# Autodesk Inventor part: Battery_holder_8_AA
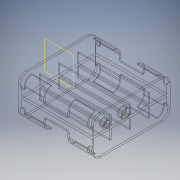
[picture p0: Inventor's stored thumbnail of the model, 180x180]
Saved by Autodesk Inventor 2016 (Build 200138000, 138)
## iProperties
Created: 2016-12
Part Number: Battery_holder_8_AA
Material: Generic
Document SubType Name: Modeling
Designer: jose
Density: 1 g/cm^3
Appearance: Default
Author: jose
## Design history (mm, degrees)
sketch "Sketch4"
  geometry: L1 (0, 0)-(14.542, 0); L2 (14.542, 0)-(14.542, -59.182); L3 (14.542, -59.182)-(0, -59.182); L4 (0, -59.182)-(0, 0)
  constraints: 8 end point, 2 parallel, 1 horizontal, 1 perpendicular
  dimensions: "d5" = 14.5415 distance of L1.start L1.end; "d6" = 59.182 distance of L3.end L1.start
extrude "Extrusion2" new body sketch "Sketch4" distance "d7" = 57.785; taper "d8" = 0 deg
fillet "Fillet1" dims "d9" = 5.842
shell "Shell1" dims "d10" = 1.5748, "d23" = 0.9652
sketch "Sketch5"
  geometry: L1 (19.621, 14.541)-(38.163, 14.541); L2 (38.163, 14.541)-(38.164, 4.318); L3 (38.164, 4.318)-(19.621, 4.318); L4 (19.621, 4.318)-(19.621, 14.541); L5 (28.893, 0)-(28.893, 14.541); L6 (57.785, 0)-(0, 0) reference; L7 (56.21, 14.541)-(1.575, 14.541) reference; L8 (4.369, 14.541)-(1.575, 14.541); L9 (1.575, 14.541)-(1.575, 6.096); L10 (1.575, 6.096)-(4.369, 6.096); L11 (4.369, 6.096)-(4.369, 14.541); L12 (56.21, 14.541)-(53.416, 14.541); L13 (53.416, 14.541)-(53.416, 6.096); L14 (53.416, 6.096)-(56.21, 6.096); L15 (56.21, 6.096)-(56.21, 14.541); L16 (57.785, 8.699)-(57.785, 0) reference; L17 (1.575, 8.699)-(1.575, 0.965) reference; L18 (56.21, 0.965)-(56.21, 8.699) reference
  constraints: 26 end point, 6 collinear, 5 parallel, 3 horizontal, 3 perpendicular, 2 midpoint, 1 point on line, 1 other
  dimensions: "d11" = 4.318 distance between parallel lines of L6 L3; "d12" = 18.542 distance of L1.start L1.end; "d15" = 6.096 distance between parallel lines of L6 L10; "d16" = 2.794 distance of L9.end L10.end
extrude "Extrusion3" cut sketch "Sketch5" stored distance "d13" = 57.785; taper "d14" = 0 deg
fillet "Fillet2" dims "d17" = 1.397
sketch "Sketch6"
  geometry: L1 (0, 4.877)-(0, 52.375) reference; L2 (0, 28.626)-(54.635, 28.626); L3 (54.635, 0)-(54.635, 57.252) reference; L4 (0, 28.118)-(54.635, 28.118); L5 (54.635, 28.118)-(54.635, 29.134); L6 (54.635, 29.134)-(0, 29.134); L7 (0, 29.134)-(0, 28.118); L8 (0, 13.386)-(54.635, 13.386); L9 (54.635, 13.386)-(54.635, 14.402); L10 (54.635, 14.402)-(0, 14.402); L11 (0, 14.402)-(0, 13.386); L12 (0, 42.85)-(54.635, 42.85); L13 (54.635, 42.85)-(54.635, 43.866); L14 (54.635, 43.866)-(0, 43.866); L15 (0, 43.866)-(0, 42.85); 1 further point
  constraints: 26 end point, 6 parallel, 6 point on line, 3 horizontal, 3 perpendicular, 2 collinear, 2 midpoint, 1 other
  dimensions: "d18" = 1.016 distance between parallel lines of L6 L4; "d19" = 13.716 distance between parallel lines of L10 L4; "d20" = 13.716 distance between parallel lines of L12 L6
extrude "Extrusion4" join sketch "Sketch6" distance "d21" = 7.4168; taper "d22" = 0 deg
sketch "Sketch8"
  geometry: L1 (0, 0.965)-(0, 0) reference; L2 (47.498, 0.965)-(0, 0.965) reference; L3 (-4.877, -4.877)-(-4.877, -9.258) reference; L4 (0, 0.457)-(0, 0); A1 r 5.355 centre (0.479, -4.877) between (0, 0.457) and (-4.877, -4.877); A2 r 4.877 centre (0, -4.877) between (0, 0) and (-4.877, -4.877) reference; 1 further point
  constraints: 2 end point, 2 point on circle, 1 centre point, 1 point on line, 1 tangent, 1 vertical
  dimensions: "d25" = 0.508 distance from line of L2 L4.start
extrude "Extrusion5" cut sketch "Sketch8" stored distance "d26" = 7.4168; taper "d27" = 0 deg
workplane "Work Plane1"
mirror "Mirror1"
fillet "Fillet3" dims "d28" = 1.397
mirror "Mirror2"
sketch "Sketch9"
  geometry: L1 (7.658, 7.976)-(19.923, 7.976); L2 (14.351, 0.965)-(0.965, 0.965) reference; L3 (7.658, 0.965)-(7.658, 15.624); L4 (29.083, 0.965)-(15.367, 0.965) reference; L5 (22.225, 0.965)-(22.225, 15.395); C1 r 2.921 at (7.658, 7.976); C2 r 2.159 at (7.658, 7.976); C3 r 2.921 at (22.225, 7.976); C4 r 3.683 at (22.225, 7.976); C5 r 7.01 at (7.658, 7.976); 1 further point
  constraints: 6 end point, 5 centre point, 3 coincident, 3 point on line, 2 midpoint, 2 vertical, 1 horizontal, 1 tangent
  dimensions: "d29" = 5.842 diameter of C1; "d30" = 4.318 diameter of C2; "d31" = 5.842 diameter of C3; "d32" = 7.366 diameter of C4; "d36" = 14.0208 diameter of C5
extrude "Extrusion6" join sketch "Sketch9" distance "d34" = 2.794; taper "d35" = 0 deg
body "Solid2"
